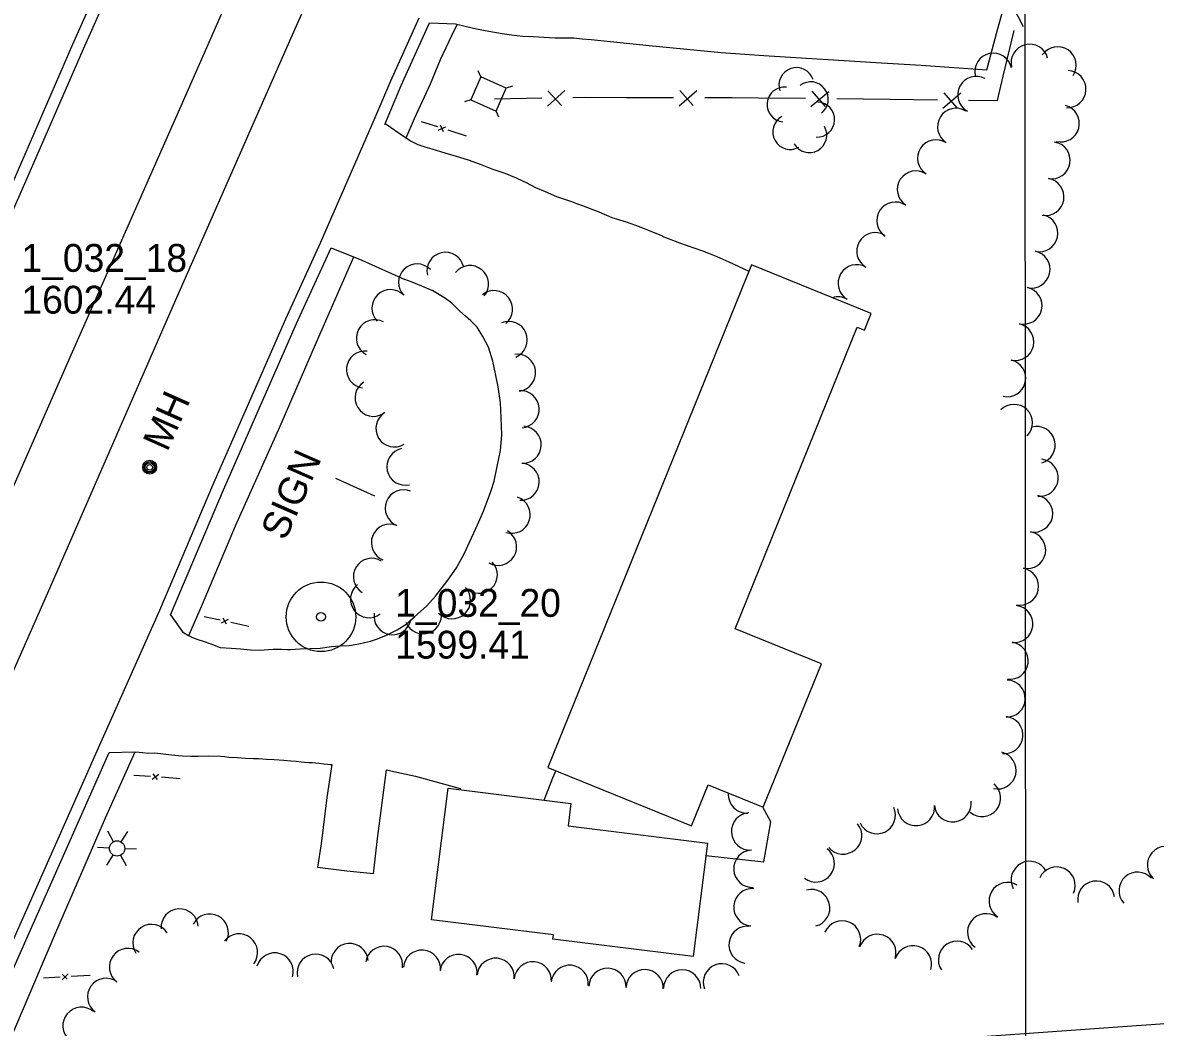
# Model space of a CAD drawing. Extents: x 189384 to 193282, y 256970 to 260388.
# Drawn here: x 190431.5 to 190675.6, y 257623.7 to 257840.1 of the extents above; entities that cross this region are included whole.
import ezdxf

# ---------------------------------------------------------------- set-up
doc = ezdxf.new("R2010")
doc.units = 0
for name, color, linetype in [('E_DRN_Grate', 7, 'Continuous'), ('E_DWY', 7, 'Continuous'), ('E_LAND_Vegetation', 7, 'Continuous'), ('E_MAP_GridLines', 7, 'Continuous'), ('E_MAP_PassPoints', 7, 'Continuous'), ('E_MISCPROP', 7, 'Continuous'), ('E_MISCPROP_HvyLine', 7, 'Continuous'), ('E_MISCPROP_Railing', 7, 'Continuous'), ('E_PATH_Sidewalk', 7, 'Continuous'), ('E_RDWY', 7, 'Continuous'), ('E_UTL_AboveGroundPipe', 7, 'Continuous')]:
    doc.layers.add(name, color=color, linetype=linetype)

# ---------------------------------------------------------------- blocks, each defined once
blk = doc.blocks.new('PP_3')
at = {"layer": 'E_MAP_PassPoints'}
for radius in [7.5, 0.96]:
    blk.add_circle((0, 0), radius, dxfattribs=at)
blk = doc.blocks.new('PED')
at = {"layer": 'E_UTL_AboveGroundPipe'}
for p, q in [((-2.34, 2.71), (-3.29, 3.77)), ((3.06, 2.71), (4.02, 3.77)), ((-3.29, -4.35), (-2.34, -3.29)), ((4.02, -4.35), (3.06, -3.29))]:
    blk.add_line(p, q, dxfattribs=at)
blk.add_lwpolyline([(-2.34, -3.29), (3.06, -3.29), (3.06, 2.71), (-2.34, 2.71)], close=True, dxfattribs=at)
blk = doc.blocks.new('LTP_6')
at = {"layer": 'E_MISCPROP'}
for p, q in [((-0.8, 1.43), (-2, 3.73)), ((0.9, 1.42), (2.27, 3.65)), ((-1.63, 0.07), (-4.24, 0.14)), ((-0.88, -1.42), (-2.24, -3.61)), ((0.76, -1.47), (2, -3.65)), ((1.64, -0.02), (4.16, -0.09))]:
    blk.add_line(p, q, dxfattribs=at)
blk.add_circle((0, 0), 1.64, dxfattribs=at)
blk = doc.blocks.new('SIGN_5')
at = {"layer": 'E_MISCPROP'}
blk.add_text('SIGN', height=6, rotation=0.0001, dxfattribs=at).set_placement((-9.61, -3.01))
blk = doc.blocks.new('MHO_1')
at = {"layer": 'E_DRN_Grate'}
for centre, radius in [((0.04, -0.06), 1.5), ((0.04, -0.06), 1.22), ((0.04, -0.07), 0.968), ((0.01, -0.08), 0.605)]:
    blk.add_circle(centre, radius, dxfattribs=at)

msp = doc.modelspace()

# ---------------------------------------------------------------- linework, layer by layer
at = {"layer": 'E_DWY'}
for points in [[(190519.18, 257840.04), (190524.73, 257839.78), (190527.12, 257839.21), (190529.28, 257838.76), (190531.95, 257838.24), (190534.83, 257837.72), (190536.83, 257837.44), (190539.28, 257837.18), (190541.49, 257837.07), (190543.83, 257836.96), (190546.25, 257836.8), (190548.4, 257836.8), (190550.23, 257836.79), (190552.06, 257836.58), (190553.99, 257836.41), (190566.51, 257835.12), (190582.04, 257833.67), (190591.23, 257832.99), (190616.52, 257831.44), (190625.07, 257830.88), (190639.22, 257829.92), (190641.31, 257837.75), (190646.22, 257855.42)], [(190509.63, 257818.33), (190514.01, 257815.35), (190515.18, 257814.52), (190516.64, 257813.85), (190518.17, 257813.32), (190519.66, 257812.85), (190522.45, 257812.03), (190524.91, 257811.27), (190527.47, 257810.52), (190530.1, 257809.58), (190532.6, 257808.55), (190535.36, 257807.62), (190537.83, 257806.61), (190539.18, 257806.01), (190539.98, 257805.61), (190542, 257804.56), (190544.09, 257803.69), (190546.52, 257802.63), (190548.28, 257802.06), (190549.74, 257801.51), (190550.86, 257801.08), (190552.3, 257800.59), (190555.67, 257799.33), (190558.45, 257798.1), (190561.5, 257797.16), (190564.31, 257796.15), (190566.31, 257795.38), (190569.01, 257794.26), (190569.67, 257793.96), (190573, 257792.61), (190576.33, 257791.52), (190577.99, 257790.93), (190579.25, 257790.4), (190581.07, 257789.66), (190583.64, 257788.51), (190587.98, 257786.52)], [(190497.95, 257791.58), (190504.57, 257788.94), (190513.85, 257784.75)], [(190463.35, 257712.51), (190465.94, 257708.86), (190467.06, 257708.15), (190468.08, 257707.65), (190469.25, 257707.22), (190470.41, 257706.85), (190472.06, 257706.26), (190474.08, 257705.49), (190476.4, 257705.32), (190478.41, 257705.16), (190480.57, 257704.97), (190482.55, 257704.89), (190485.46, 257705.14), (190487.28, 257705.1), (190488.54, 257705.07), (190489.14, 257705.04), (190491.29, 257705.21), (190493.47, 257705.26), (190495.61, 257705.35), (190498.02, 257705.66), (190499.78, 257705.82), (190501.82, 257705.9), (190503.93, 257706.27), (190505.13, 257706.53), (190506.43, 257706.87), (190507.96, 257707.34), (190509.88, 257708.15), (190512.19, 257709.26), (190514.15, 257710.48), (190515.95, 257712.06), (190518.59, 257714.46), (190520.43, 257716.56), (190523.13, 257719.96), (190524.98, 257722.66), (190526.62, 257725.65), (190527.86, 257728.28), (190529.53, 257731.88), (190530.76, 257734.83), (190531.64, 257737.13), (190532.39, 257739.05), (190533.12, 257741.32), (190533.73, 257744.46), (190534.43, 257747.88), (190534.73, 257751.3), (190534.63, 257755), (190534.43, 257758.14), (190533.95, 257761.59), (190533.41, 257764.39), (190532.84, 257767.15), (190531.88, 257770.2), (190530.66, 257772.47), (190529.43, 257774.44), (190528.09, 257775.87), (190526.92, 257776.83), (190525.67, 257777.93), (190523.99, 257779.65), (190522.63, 257780.65), (190519.9, 257782.29), (190517.5, 257783.33), (190515.45, 257784.17), (190513.85, 257784.75)], [(190450.16, 257682.87), (190455.51, 257682.98), (190456.61, 257682.9), (190457.39, 257682.84), (190458.46, 257682.73), (190459.99, 257682.76), (190461.76, 257682.58), (190462.89, 257682.44), (190464.32, 257682.3), (190465.87, 257682.13), (190467.72, 257682.1), (190469.3, 257682.08), (190471.54, 257682.11), (190474.13, 257682.03), (190475.01, 257681.98), (190475.9, 257681.84), (190477.79, 257681.75), (190479.49, 257681.67), (190481.24, 257681.57), (190482.4, 257681.53), (190484.02, 257681.44), (190485.68, 257681.38), (190487.78, 257681.19), (190489.27, 257681.06), (190490.42, 257680.98), (190491.51, 257680.87), (190492.26, 257680.8), (190493.15, 257680.71), (190493.43, 257680.69), (190493.85, 257680.69), (190495.28, 257680.58), (190496.4, 257680.43), (190497.22, 257680.33), (190497.86, 257680.28), (190498.15, 257680.27), (190497.04, 257673.16), (190495.83, 257663.19), (190495.02, 257658.16), (190501.38, 257657.4), (190507.08, 257656.77), (190507.1, 257656.75), (190507.96, 257664.35), (190509.92, 257679.13), (190512.11, 257678.63), (190516.16, 257677.74), (190525.79, 257675.11), (190525.77, 257674.82)], [(190543.9, 257672.56), (190545.75, 257677.37), (190546.4, 257678.89)], [(190578.7, 257660.67), (190591.19, 257659.33), (190592.72, 257667.91), (190591.01, 257671.09)], [(190307.65, 257339.7), (190336.95, 257405.99), (190371.25, 257481.51), (190412.4, 257575.11), (190426.44, 257606.63), (190736.05, 257628.66), (190837.56, 257638.62), (191029.69, 257654.26)]]:
    msp.add_lwpolyline(points, dxfattribs=at)
at = {"layer": 'E_LAND_Vegetation'}
for centre, radius, start, end in [((190648.47, 257831.43), 4, 14.1697, 194.1544), ((190654.52, 257830.89), 4, 326.1806, 146.1652), ((190640.63, 257829.5), 4, 11.9731, 191.9578), ((190598.23, 257826.6), 3.78, 18.8177, 198.8023), ((190656.61, 257825.73), 4, 267.5394, 87.5241), ((190601.3, 257823.54), 3.78, 307.3636, 127.3483), ((190636.96, 257824.51), 4, 61.5402, 241.5249), ((190595.7, 257822.43), 3.78, 84.3083, 264.293), ((190602.68, 257819.18), 3.78, 267.3636, 87.3483), ((190655.18, 257818.36), 4, 255.144, 75.1287), ((190596.92, 257816.53), 3.78, 119.1119, 299.0966), ((190632.62, 257817.63), 4, 57.9114, 237.8961), ((190600.99, 257815.85), 3.78, 209.5386, 29.5232), ((190628.33, 257810.83), 4, 56.8203, 236.805), ((190653.19, 257810.41), 4, 260.462, 80.4466), ((190623.95, 257804.13), 4, 56.8203, 236.805), ((190651.86, 257802.52), 4, 260.462, 80.4466), ((190619.54, 257797.43), 4, 56.4596, 236.4443), ((190650.55, 257794.72), 4, 257.8057, 77.7904), ((190615.21, 257790.85), 4, 59.8622, 239.8468), ((190522.61, 257786.61), 3.99, 13.2336, 193.2183), ((190648.86, 257786.9), 4, 257.8057, 77.7904), ((190516.48, 257784.11), 3.99, 44.0864, 224.0711), ((190527.88, 257783.75), 3.99, 320.7295, 140.7142), ((190611.19, 257783.93), 4, 59.8622, 239.8468), ((190647.14, 257779.1), 4, 257.2903, 77.275), ((190510.76, 257778.57), 3.99, 44.0864, 224.0711), ((190533.09, 257778.36), 3.99, 308.7584, 128.7431), ((190607.17, 257777.01), 4, 59.8622, 107.6076), ((190507.38, 257772.08), 3.99, 62.0947, 242.0794), ((190536.24, 257771.72), 3.99, 292.9451, 112.9298), ((190645.38, 257771.29), 4, 257.2903, 77.275), ((190505.25, 257765.33), 3.99, 82.9251, 262.9097), ((190538.04, 257764.65), 3.99, 276.6522, 96.6369), ((190643.62, 257763.48), 4, 257.2757, 77.2603), ((190507.1, 257759.25), 3.99, 121.6228, 301.6075), ((190538.81, 257756.8), 3.99, 274.474, 94.4587), ((190511.6, 257752.67), 3.99, 121.564, 301.5487), ((190645.1, 257753.84), 4, 315.7528, 135.7374), ((190539.24, 257749.13), 3.99, 266.8624, 86.8471), ((190649.99, 257749.08), 4, 285.7197, 105.7044), ((190513.97, 257744.41), 3.99, 102.4015, 282.3862), ((190538.81, 257741.17), 3.99, 266.8624, 86.8471), ((190650.64, 257742.05), 4, 263.8293, 83.814), ((190513.61, 257735.46), 3.99, 68.0409, 248.0256), ((190536.88, 257734.06), 3.99, 251.5644, 71.5491), ((190649.45, 257734.32), 4, 259.0605, 79.0452), ((190510.62, 257728.07), 3.99, 68.0409, 248.0256), ((190533.95, 257727.15), 3.99, 239.9168, 59.9015), ((190647.93, 257726.46), 4, 259.0605, 79.0452), ((190506.75, 257720.71), 3.99, 58.2049, 238.1896), ((190529.8, 257721.13), 3.99, 223.525, 43.5097), ((190646.4, 257718.61), 4, 258.9335, 78.9182), ((190506.12, 257715.88), 3.99, 127.7337, 307.7183), ((190524.02, 257715.64), 3.99, 223.525, 43.5097), ((190645.17, 257710.54), 4, 263.3281, 83.3128), ((190511.2, 257712.2), 3.99, 170.0493, 350.034), ((190517.75, 257712.41), 3.99, 201.5868, 21.5715), ((190644.18, 257702.62), 4, 262.6391, 82.6238), ((190643.52, 257694.46), 4, 267.991, 87.9756), ((190643.02, 257686.6), 4, 264.5071, 84.4917), ((190641.57, 257679), 4, 257.1804, 77.1651), ((190638.23, 257673.06), 4, 230.1777, 50.1624), ((190587.54, 257673.82), 4.01, 175.739, 273.2583), ((190615.56, 257669.35), 4, 204.8328, 24.8175), ((190624, 257671.09), 4, 185.0797, 5.0644), ((190631.91, 257671.91), 4, 186.4328, 6.4175), ((190588.21, 257665.85), 4.01, 93.8891, 273.8738), ((190608.31, 257664.97), 4, 219.5528, 39.5375), ((190588.71, 257657.81), 4.01, 92.7929, 272.7776), ((190602.4, 257658.95), 4, 232.7266, 52.7112), ((190677.83, 257658.63), 4, 48.5761, 228.5608), ((190648.48, 257655.43), 4, 27.6732, 207.6579), ((190654.29, 257654.21), 4, 335.6013, 155.586), ((190671.72, 257653.09), 4, 41.7981, 221.7828), ((190588.7, 257649.54), 4.01, 85.484, 265.4687), ((190643.71, 257650.88), 4, 58.6915, 238.6762), ((190662.82, 257651.18), 4, 8.7357, 188.7204), ((190601.43, 257649.36), 4, 284.5576, 104.5423), ((190465.33, 257645.16), 4.01, 3.9096, 183.8942), ((190471.82, 257644.05), 4.01, 332.4684, 152.453), ((190608.07, 257642.61), 4, 337.5735, 157.5582), ((190639.08, 257644.14), 4, 53.8955, 233.8802), ((190459.24, 257641.82), 4.01, 32.7733, 212.758), ((190478.12, 257639.79), 4.01, 321.8841, 141.8688), ((190587.69, 257641.45), 4.01, 81.6362, 261.6208), ((190501.94, 257637.7), 4.01, 4.6815, 184.6662), ((190615.68, 257639.71), 4, 341.601, 161.5856), ((190632.8, 257638.22), 4, 33.1374, 213.1221), ((190454.2, 257636.65), 4.01, 53.2238, 233.2085), ((190485.81, 257635.68), 4.01, 342.8606, 162.8453), ((190494.63, 257635.42), 4.01, 12.3386, 192.3233), ((190509.37, 257637.1), 4.01, 350.6892, 170.6739), ((190517.52, 257636.27), 4.01, 355.4759, 175.4606), ((190525.41, 257635.35), 4.01, 353.3654, 173.3501), ((190623.35, 257637.25), 4, 342.9959, 162.9806), ((190533.41, 257634.53), 4.01, 354.2497, 174.2343), ((190541.42, 257633.78), 4.01, 354.8792, 174.8639), ((190549.38, 257633.03), 4.01, 354.3198, 174.3045), ((190582.15, 257633.34), 4.01, 20.4541, 200.4388), ((190449.48, 257630.22), 4.01, 54.3363, 234.321), ((190557.51, 257632.38), 4.01, 358.0156, 178.0003), ((190565.52, 257632.1), 4.01, 358.0156, 178.0003), ((190573.6, 257632.04), 4.01, 359.6168, 179.6015), ((190444.16, 257623.99), 4.01, 49.4292, 229.4139)]:
    msp.add_arc(centre, radius, start, end, dxfattribs=at)
at = {"layer": 'E_MAP_GridLines'}
for p, q in [((190647.76, 257511.45), (190646.69, 259011.44)), ((190648.11, 257011.45), (190647.05, 258511.45))]:
    msp.add_line(p, q, dxfattribs=at)
at = {"layer": 'E_MISCPROP'}
msp.add_line((190507.38, 257738.09), (190498.98, 257741.84), dxfattribs=at)
at = {"layer": 'E_MISCPROP_HvyLine'}
for points in [[(190588.53, 257787.88), (190544.67, 257679.59), (190575.63, 257667.05), (190579.21, 257675.87), (190591.08, 257671.06), (190603.6, 257701.97), (190584.99, 257709.51), (190611.31, 257774.49), (190612.86, 257773.86), (190614.31, 257777.44)], [(190549.04, 257667.09), (190579.03, 257663.35), (190575.98, 257638.88), (190545.77, 257642.65), (190545.89, 257643.55), (190519.62, 257646.83), (190523.15, 257675.14), (190549.63, 257671.84)]]:
    msp.add_lwpolyline(points, close=True, dxfattribs=at)
at = {"layer": 'E_MISCPROP_Railing'}
for p, q in [((190647.16, 257839.14), (190644.84, 257843.6)), ((190544.55, 257822.08), (190548.29, 257825.45)), ((190544.67, 257825.39), (190547.57, 257822.2)), ((190572.94, 257822.16), (190576.74, 257825.46)), ((190573.12, 257825.47), (190575.97, 257822.22)), ((190601.35, 257821.99), (190605.18, 257825.25)), ((190601.56, 257825.29), (190604.38, 257822.03)), ((190629.78, 257821.67), (190633.61, 257824.93)), ((190629.99, 257824.97), (190632.8, 257821.71)), ((190521.06, 257816.93), (190522.71, 257817.66)), ((190521.47, 257818.04), (190522.1, 257816.63)), ((190474.33, 257710.75), (190475.85, 257711.59)), ((190474.63, 257711.85), (190475.36, 257710.55)), ((190459.4, 257677.09), (190460.82, 257678.16)), ((190459.55, 257678.25), (190460.47, 257677.04)), ((190440.02, 257633.92), (190441.3, 257635.17)), ((190440.02, 257635.09), (190441.1, 257634))]:
    msp.add_line(p, q, dxfattribs=at)
for points in [[(190642.77, 257828.53), (190645.16, 257838.41)], [(190635.33, 257823.38), (190641.51, 257823.31), (190642.77, 257828.53)], [(190533.18, 257823.68), (190543.33, 257823.84)], [(190550.05, 257823.95), (190552.74, 257823.99), (190561.6, 257823.97)], [(190561.6, 257823.97), (190571.76, 257823.94)], [(190578.48, 257823.93), (190584.41, 257823.96), (190590.03, 257823.89)], [(190590.03, 257823.89), (190600.19, 257823.78)], [(190606.9, 257823.7), (190618.45, 257823.57)], [(190618.45, 257823.57), (190628.61, 257823.46)], [(190517.37, 257818.76), (190520.85, 257817.67)], [(190523.14, 257816.95), (190527.09, 257815.71)], [(190470.63, 257712.18), (190474.06, 257711.44)], [(190476.33, 257710.94), (190480.23, 257710.09)], [(190455.45, 257678), (190459.03, 257677.75)], [(190461.4, 257677.58), (190465.47, 257677.29)], [(190435.96, 257634.31), (190439.57, 257634.52)], [(190441.95, 257634.66), (190446.05, 257634.9)]]:
    msp.add_lwpolyline(points, dxfattribs=at)
at = {"layer": 'E_PATH_Sidewalk'}
for points in [[(190514.12, 257815.27), (190515.95, 257819.45), (190519.36, 257826.87), (190521.54, 257832.13), (190523.96, 257837.32), (190525.14, 257839.68)], [(190467.27, 257708.05), (190470.24, 257714.83), (190477.36, 257731.68), (190486.97, 257753.14), (190494.79, 257771.26), (190502.88, 257789.62)], [(190298.77, 257325.23), (190309.52, 257350.29), (190325.17, 257386.26), (190343.36, 257427.37), (190362.39, 257470.22), (190394.6, 257542.28), (190411.69, 257580.96), (190438.45, 257643.57), (190449.34, 257668.76), (190455.73, 257682.97)]]:
    msp.add_lwpolyline(points, dxfattribs=at)
at = {"layer": 'E_RDWY'}
for points in [[(190639.31, 258218.07), (190609.41, 258149.39), (190580.27, 258083.06), (190547.78, 258009.13), (190519.09, 257944.03), (190494.25, 257887.28), (190465.55, 257822.08), (190442.19, 257769.07), (190419.9, 257718.5), (190394.49, 257660.93), (190374.24, 257614.8), (190349, 257556.99), (190323.12, 257498.57), (190298.43, 257442.39), (190276.94, 257393.85), (190259.86, 257355.22)], [(190647.06, 258194.52), (190624.13, 258142.92), (190594.92, 258076.29), (190570.69, 258021.28), (190551.11, 257977.35), (190533.78, 257937.86), (190511.8, 257887.72), (190488.43, 257834.81), (190463.86, 257779), (190437.37, 257718.32), (190410.84, 257658.32), (190384.1, 257597.28), (190367.03, 257558.94), (190342.84, 257503.57), (190317.05, 257445.11), (190294.43, 257394.4)], [(190250.08, 257392.44), (190265, 257426.05), (190280.63, 257461.47), (190298.01, 257501.1), (190315.61, 257540.66), (190329.32, 257571.82), (190346.52, 257610.97), (190369.12, 257662.7), (190389.76, 257709.75), (190408.17, 257751.62), (190431.5, 257804.24), (190444.63, 257834.42), (190462.73, 257875.09), (190477.51, 257908.64), (190486.34, 257929.3)], [(190262.71, 257427.06), (190278.34, 257462.48), (190295.73, 257502.11), (190313.33, 257541.67), (190327.03, 257572.83), (190344.23, 257611.97), (190366.83, 257663.7), (190387.47, 257710.75), (190405.88, 257752.63), (190429.21, 257805.24), (190442.34, 257835.43), (190460.44, 257876.1), (190475.22, 257909.64), (190484.04, 257930.29)], [(190495.68, 257792.62), (190507.25, 257819.11), (190510.8, 257827.52), (190516.9, 257841.07)], [(190509.55, 257818.14), (190513.09, 257826.52), (190519.18, 257840.04)], [(190447.87, 257683.88), (190461.04, 257713.48), (190472.45, 257740.45), (190488.23, 257776.28), (190495.68, 257792.62)], [(190463.35, 257712.51), (190474.74, 257739.46), (190490.51, 257775.26), (190497.95, 257791.58)], [(190298.55, 257344.93), (190324.04, 257403.04), (190340.35, 257440.33), (190356.36, 257476.6), (190385.44, 257542.83), (190404.46, 257585.57), (190428.47, 257640.15), (190447.87, 257683.88)], [(190300.84, 257343.92), (190326.33, 257402.04), (190342.64, 257439.32), (190358.64, 257475.59), (190387.73, 257541.82), (190406.75, 257584.56), (190430.76, 257639.14), (190450.16, 257682.87)]]:
    msp.add_lwpolyline(points, dxfattribs=at)

# ---------------------------------------------------------------- block references
at = {"layer": 'E_DRN_Grate', "rotation": 66.02695025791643}
msp.add_blockref('MHO_1', (190458.8, 257744.29), dxfattribs=at)
at = {"layer": 'E_MAP_PassPoints', "rotation": -0.00010131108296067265}
msp.add_blockref('PP_3', (190495.78, 257712.08), dxfattribs=at)
at = {"layer": 'E_MISCPROP', "xscale": 1.0000015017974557, "yscale": 1.000001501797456, "rotation": 66.23275177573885}
msp.add_blockref('SIGN_5', (190489.22, 257738.28), dxfattribs=at)
at = {"layer": 'E_MISCPROP', "rotation": -0.38697138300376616}
msp.add_blockref('LTP_6', (190451.84, 257662.19), dxfattribs=at)
at = {"layer": 'E_UTL_AboveGroundPipe', "rotation": 66.26477179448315}
msp.add_blockref('PED', (190531.46, 257824.48), dxfattribs=at)

# ---------------------------------------------------------------- texts
at = {"layer": 'E_DRN_Grate'}
msp.add_text('MH', height=6, rotation=66.027, dxfattribs=at).set_placement((190462.68, 257747.44))
at = {"layer": 'E_MAP_PassPoints'}
for s, p in [('1_032_18', (190431.24, 257786.39)), ('1602.44', (190431.24, 257777.39)), ('1_032_20', (190511.78, 257712.08)), ('1599.41', (190511.78, 257703.08))]:
    msp.add_text(s, height=6, rotation=0, dxfattribs=at).set_placement(p)

doc.saveas('drawing.dxf')
